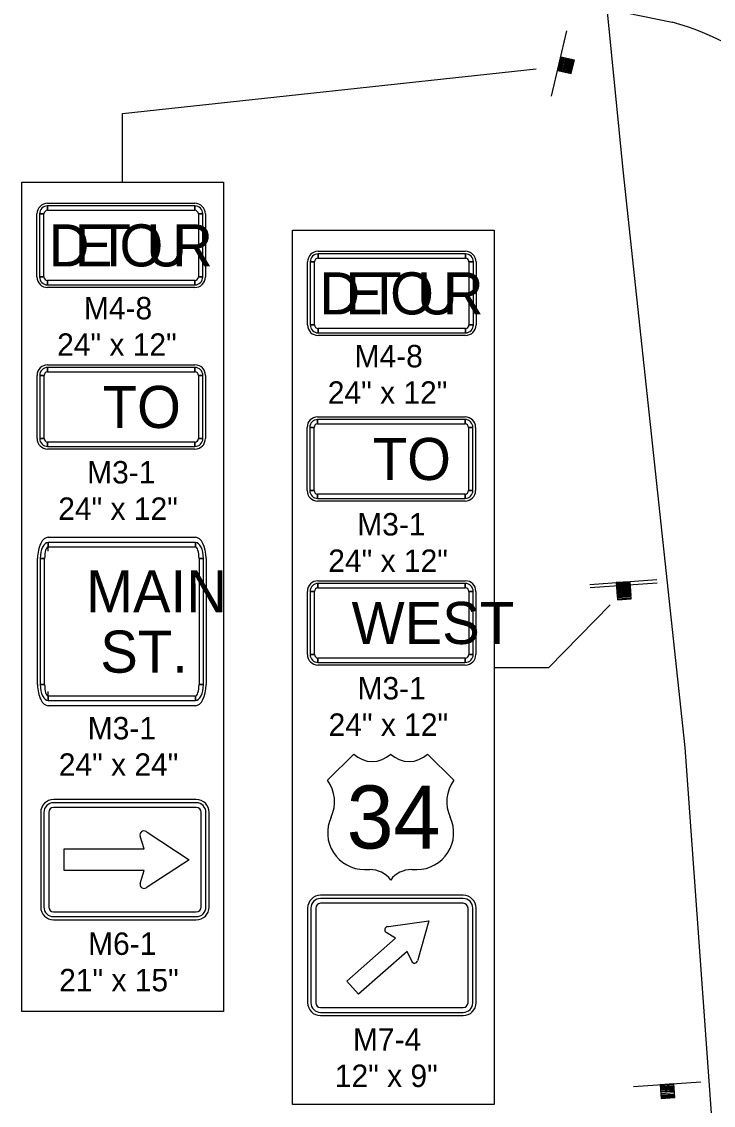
# Model space of a CAD drawing. Extents: x 10133 to 81668, y 6132 to 11018.
# Drawn here: x 11723.8 to 11970.7, y 8730.4 to 9117.3 of the extents above; entities that cross this region are included whole.
import ezdxf

# ---------------------------------------------------------------- set-up
doc = ezdxf.new("R2010")
doc.units = 0
for name, color, linetype in [('dsnTextFinalPlan', 7, 'Continuous'), ('Level 10', 7, 'Continuous'), ('Level 4', 7, 'Continuous'), ('Level 5', 7, 'Continuous')]:
    doc.layers.add(name, color=color, linetype=linetype)

msp = doc.modelspace()

# ---------------------------------------------------------------- linework, layer by layer
at = {"layer": 'dsnTextFinalPlan'}
for p, q in [((11804.44, 9148.37), (11956.07, 9117.16)), ((11912.99, 9090.73), (11918.44, 9114.1)), ((11916.6, 9104.63), (11915.49, 9099.88)), ((11915.73, 9099.82), (11916.84, 9104.57)), ((11917.06, 9104.52), (11915.96, 9099.77)), ((11916.18, 9099.72), (11917.29, 9104.47)), ((11917.48, 9104.42), (11916.37, 9099.67)), ((11916.55, 9099.63), (11917.65, 9104.38)), ((11917.94, 9104.32), (11916.83, 9099.57)), ((11917.06, 9099.51), (11918.16, 9104.26)), ((11918.35, 9104.22), (11917.23, 9099.47)), ((11917.52, 9099.41), (11918.62, 9104.16)), ((11918.94, 9104.08), (11917.84, 9099.33)), ((11918.2, 9099.25), (11919.31, 9104)), ((11919.5, 9103.95), (11918.38, 9099.21)), ((11918.75, 9099.12), (11919.87, 9103.87)), ((11920.04, 9103.83), (11918.94, 9099.08)), ((11919.21, 9099.01), (11920.31, 9103.76)), ((11920.5, 9103.72), (11919.4, 9098.97)), ((11919.67, 9098.91), (11920.78, 9103.66)), ((11926.67, 8916.41), (11950.6, 8918.14)), ((11926.75, 8915.23), (11950.69, 8916.97)), ((11941.01, 8917.08), (11936.15, 8916.73)), ((11936.16, 8916.49), (11941.03, 8916.84)), ((11941.04, 8916.61), (11936.18, 8916.26)), ((11936.2, 8916.03), (11941.06, 8916.38)), ((11941.07, 8916.19), (11936.21, 8915.83)), ((11936.22, 8915.65), (11941.09, 8916.01)), ((11941.09, 8915.91), (11936.23, 8915.56)), ((11941.11, 8915.71), (11936.24, 8915.36)), ((11936.25, 8915.31), (11941.11, 8915.66)), ((11936.26, 8915.13), (11941.13, 8915.48)), ((11941.13, 8915.44), (11936.27, 8915.08)), ((11941.14, 8915.29), (11936.27, 8914.95)), ((11936.28, 8914.85), (11941.15, 8915.21)), ((11941.16, 8915.01), (11936.3, 8914.66)), ((11936.3, 8914.66), (11941.16, 8915.01)), ((11936.31, 8914.48), (11941.17, 8914.83)), ((11941.18, 8914.68), (11936.32, 8914.33)), ((11941.19, 8914.54), (11936.33, 8914.19)), ((11936.35, 8913.96), (11941.21, 8914.31)), ((11936.35, 8913.96), (11941.21, 8914.31)), ((11941.23, 8914.11), (11936.36, 8913.78)), ((11941.23, 8914.11), (11936.36, 8913.78)), ((11936.38, 8913.48), (11941.25, 8913.84)), ((11936.39, 8913.4), (11941.25, 8913.74)), ((11941.27, 8913.56), (11936.4, 8913.21)), ((11941.27, 8913.51), (11936.4, 8913.16)), ((11936.42, 8912.93), (11941.29, 8913.28)), ((11936.43, 8912.78), (11941.3, 8913.13)), ((11941.3, 8913.09), (11936.44, 8912.73)), ((11941.31, 8912.94), (11936.45, 8912.6)), ((11936.46, 8912.45), (11941.32, 8912.81)), ((11936.47, 8912.23), (11941.34, 8912.56)), ((11941.35, 8912.38), (11936.49, 8912.03)), ((11936.51, 8911.75), (11941.37, 8912.11)), ((11941.38, 8911.91), (11936.52, 8911.56)), ((11936.54, 8911.28), (11941.41, 8911.63)), ((11881.44, 8805.37), (11830.48, 8805.37)), ((11825.9, 8800.79), (11825.9, 8767)), ((11886.03, 8767), (11886.03, 8800.79)), ((11830.48, 8762.42), (11881.44, 8762.42)), ((11942.28, 8737.1), (11966.22, 8738.78)), ((11956.63, 8737.75), (11951.76, 8737.41)), ((11951.78, 8737.16), (11956.64, 8737.5)), ((11956.66, 8737.27), (11951.79, 8736.93)), ((11951.81, 8736.7), (11956.68, 8737.05)), ((11956.69, 8736.85), (11951.82, 8736.51)), ((11951.84, 8736.33), (11956.7, 8736.67)), ((11956.72, 8736.38), (11951.86, 8736.04)), ((11951.87, 8735.81), (11956.74, 8736.15)), ((11956.75, 8735.95), (11951.89, 8735.63)), ((11951.91, 8735.33), (11956.77, 8735.67)), ((11956.79, 8735.35), (11951.93, 8735.01)), ((11951.96, 8734.63), (11956.82, 8734.97)), ((11956.83, 8734.78), (11951.97, 8734.45)), ((11951.99, 8734.08), (11956.86, 8734.4)), ((11956.87, 8734.22), (11952.01, 8733.88)), ((11952.03, 8733.6), (11956.89, 8733.94)), ((11956.91, 8733.75), (11952.04, 8733.41)), ((11952.06, 8733.13), (11956.93, 8733.47))]:
    msp.add_line(p, q, dxfattribs=at)
for points in [[(11924.53, 9208.75), (11924.53, 9205.04), (11938.44, 9064.44), (11960.57, 8858.09), (11970.22, 8724.25)], [(11759.83, 9059.99), (11759.83, 9084.49), (11907.51, 9100.55)], [(11892.49, 8886.75), (11912, 8886.75), (11933.91, 8909.07)], [(11854.74, 8794.23), (11869.11, 8796.3), (11865.25, 8782.32)], [(11863.04, 8781.81), (11861.41, 8785.32), (11844.09, 8770.03), (11839.93, 8774.74), (11857.26, 8790.03), (11853.96, 8792.06)]]:
    msp.add_lwpolyline(points, dxfattribs=at)
for points in [[(11916.33, 9104.69), (11915.22, 9099.91), (11920, 9098.8), (11921.11, 9103.58)], [(11723.8, 9059.99), (11795.86, 9059.99), (11795.86, 8763.89), (11723.8, 8763.89)], [(11723.8, 9059.99), (11795.86, 9059.99), (11795.86, 8763.89), (11723.8, 8763.89)], [(11820.43, 9042.86), (11892.49, 9042.86), (11892.49, 8730.63), (11820.43, 8730.63)], [(11820.43, 9042.86), (11892.49, 9042.86), (11892.49, 8730.63), (11820.43, 8730.63)], [(11940.99, 8917.36), (11936.09, 8917.01), (11936.45, 8912.11), (11941.34, 8912.46)], [(11941.07, 8916.19), (11936.18, 8915.83), (11936.53, 8910.93), (11941.43, 8911.29)], [(11956.61, 8738.02), (11951.71, 8737.68), (11952.05, 8732.78), (11956.95, 8733.13)]]:
    msp.add_lwpolyline(points, close=True, dxfattribs=at)
for centre, radius, start, end in [((11932.89, 9030.85), 89.37, 17.4357, 74.9717), ((11830.48, 8800.79), 4.58, 90, 180), ((11881.44, 8800.79), 4.58, 360, 90), ((11854.58, 8793.04), 1.16, 98.0346, 237.3927), ((11838.21, 8909.01), 115.96, 278.0346, 278.1951), ((11864.06, 8782.3), 1.14, 205.4546, 344.7341), ((11977.03, 8751.46), 115.96, 164.5667, 164.7341), ((11830.48, 8767), 4.58, 180, 270), ((11881.44, 8767), 4.58, 270, 0)]:
    msp.add_arc(centre, radius, start, end, dxfattribs=at)
at = {"layer": 'Level 10'}
for p, q in [((11733.01, 9052.48), (11785.62, 9052.48)), ((11733.01, 9049.97), (11733.01, 9051.54)), ((11785.62, 9051.54), (11785.62, 9049.97)), ((11729.25, 9026.17), (11729.25, 9048.72)), ((11730.19, 9048.72), (11731.75, 9048.72)), ((11786.87, 9048.72), (11788.44, 9048.72)), ((11789.38, 9048.72), (11789.38, 9026.17)), ((11829.63, 9035.35), (11882.25, 9035.35)), ((11829.63, 9032.84), (11829.63, 9034.41)), ((11882.25, 9034.41), (11882.25, 9032.84)), ((11825.88, 9009.04), (11825.88, 9031.59)), ((11826.82, 9031.59), (11828.38, 9031.59)), ((11883.5, 9031.59), (11885.07, 9031.59)), ((11886.01, 9031.59), (11886.01, 9009.04)), ((11731.75, 9026.17), (11730.19, 9026.17)), ((11733.01, 9023.35), (11733.01, 9024.92)), ((11785.62, 9024.92), (11785.62, 9023.35)), ((11788.44, 9026.17), (11786.87, 9026.17)), ((11785.62, 9022.41), (11733.01, 9022.41)), ((11828.38, 9009.04), (11826.82, 9009.04)), ((11885.07, 9009.04), (11883.5, 9009.04)), ((11829.63, 9006.22), (11829.63, 9007.79)), ((11882.25, 9005.28), (11829.63, 9005.28)), ((11882.25, 9007.79), (11882.25, 9006.22)), ((11733.05, 8994.79), (11785.66, 8994.79)), ((11733.05, 8992.29), (11733.05, 8993.85)), ((11785.66, 8993.85), (11785.66, 8992.29)), ((11729.29, 8968.48), (11729.29, 8991.03)), ((11730.23, 8991.03), (11731.8, 8991.03)), ((11786.92, 8991.03), (11788.48, 8991.03)), ((11789.42, 8991.03), (11789.42, 8968.48)), ((11829.47, 8976.2), (11882.08, 8976.2)), ((11829.47, 8973.7), (11829.47, 8975.26)), ((11882.08, 8975.26), (11882.08, 8973.7)), ((11825.71, 8949.9), (11825.71, 8972.45)), ((11826.65, 8972.45), (11828.22, 8972.45)), ((11883.34, 8972.45), (11884.9, 8972.45)), ((11885.84, 8972.45), (11885.84, 8949.9)), ((11731.8, 8968.48), (11730.23, 8968.48)), ((11733.05, 8965.67), (11733.05, 8967.23)), ((11785.66, 8967.23), (11785.66, 8965.67)), ((11788.48, 8968.48), (11786.92, 8968.48)), ((11785.66, 8964.73), (11733.05, 8964.73)), ((11828.22, 8949.9), (11826.65, 8949.9)), ((11829.47, 8947.08), (11829.47, 8948.64)), ((11882.08, 8948.64), (11882.08, 8947.08)), ((11884.9, 8949.9), (11883.34, 8949.9)), ((11882.08, 8946.14), (11829.47, 8946.14)), ((11733.24, 8933.21), (11785.86, 8933.21)), ((11733.24, 8928.2), (11733.24, 8931.33)), ((11785.86, 8931.33), (11785.86, 8929.76)), ((11729.48, 8880.59), (11729.48, 8925.69)), ((11730.42, 8925.69), (11731.99, 8925.69)), ((11787.11, 8925.69), (11788.67, 8925.69)), ((11789.61, 8925.69), (11789.61, 8880.59)), ((11829.58, 8917.66), (11882.19, 8917.66)), ((11829.58, 8915.15), (11829.58, 8916.72)), ((11882.19, 8916.72), (11882.19, 8915.15)), ((11825.82, 8891.35), (11825.82, 8913.9)), ((11826.76, 8913.9), (11828.33, 8913.9)), ((11883.44, 8913.9), (11885.01, 8913.9)), ((11885.95, 8913.9), (11885.95, 8891.35)), ((11828.33, 8891.35), (11826.76, 8891.35)), ((11829.58, 8888.53), (11829.58, 8890.1)), ((11882.19, 8890.1), (11882.19, 8888.53)), ((11885.01, 8891.35), (11883.44, 8891.35)), ((11882.19, 8887.59), (11829.58, 8887.59)), ((11731.99, 8880.59), (11730.42, 8880.59)), ((11733.24, 8874.96), (11733.24, 8878.09)), ((11788.67, 8880.59), (11787.11, 8880.59)), ((11785.86, 8876.52), (11785.86, 8874.96)), ((11785.86, 8873.08), (11733.24, 8873.08)), ((11786.14, 8839.55), (11735.17, 8839.55)), ((11786.14, 8838.41), (11735.17, 8838.41)), ((11730.59, 8834.97), (11730.59, 8801.18)), ((11731.73, 8834.97), (11731.73, 8801.18)), ((11733.45, 8834.97), (11733.45, 8801.18)), ((11786.14, 8836.69), (11735.17, 8836.69)), ((11787.85, 8801.18), (11787.85, 8834.97)), ((11789.57, 8801.18), (11789.57, 8834.97)), ((11790.72, 8801.18), (11790.72, 8834.97)), ((11881.44, 8804.22), (11830.48, 8804.22)), ((11827.04, 8800.79), (11827.04, 8767)), ((11828.76, 8800.79), (11828.76, 8767)), ((11881.44, 8802.5), (11830.48, 8802.5)), ((11883.16, 8767), (11883.16, 8800.79)), ((11884.88, 8767), (11884.88, 8800.79)), ((11735.17, 8799.47), (11786.14, 8799.47)), ((11735.17, 8797.75), (11786.14, 8797.75)), ((11735.17, 8796.6), (11786.14, 8796.6)), ((11830.48, 8765.28), (11881.44, 8765.28)), ((11830.48, 8763.56), (11881.44, 8763.56))]:
    msp.add_line(p, q, dxfattribs=at)
for points in [[(11785.62, 9051.54), (11733.01, 9051.54), (11733.01, 9049.97), (11785.62, 9049.97), (11785.62, 9051.54)], [(11730.19, 9048.72), (11730.19, 9026.17), (11731.75, 9026.17), (11731.75, 9048.72), (11730.19, 9048.72)], [(11788.44, 9026.17), (11788.44, 9048.72), (11786.87, 9048.72), (11786.87, 9026.17), (11788.44, 9026.17)], [(11882.25, 9034.41), (11829.63, 9034.41), (11829.63, 9032.84), (11882.25, 9032.84), (11882.25, 9034.41)], [(11826.82, 9031.59), (11826.82, 9009.04), (11828.38, 9009.04), (11828.38, 9031.59), (11826.82, 9031.59)], [(11885.07, 9009.04), (11885.07, 9031.59), (11883.5, 9031.59), (11883.5, 9009.04), (11885.07, 9009.04)], [(11733.01, 9023.35), (11785.62, 9023.35), (11785.62, 9024.92), (11733.01, 9024.92), (11733.01, 9023.35)], [(11829.63, 9006.22), (11882.25, 9006.22), (11882.25, 9007.79), (11829.63, 9007.79), (11829.63, 9006.22)], [(11785.66, 8993.85), (11733.05, 8993.85), (11733.05, 8992.29), (11785.66, 8992.29), (11785.66, 8993.85)], [(11730.23, 8991.03), (11730.23, 8968.48), (11731.8, 8968.48), (11731.8, 8991.03), (11730.23, 8991.03)], [(11788.48, 8968.48), (11788.48, 8991.03), (11786.92, 8991.03), (11786.92, 8968.48), (11788.48, 8968.48)], [(11882.08, 8975.26), (11829.47, 8975.26), (11829.47, 8973.7), (11882.08, 8973.7), (11882.08, 8975.26)], [(11826.65, 8972.45), (11826.65, 8949.9), (11828.22, 8949.9), (11828.22, 8972.45), (11826.65, 8972.45)], [(11884.9, 8949.9), (11884.9, 8972.45), (11883.34, 8972.45), (11883.34, 8949.9), (11884.9, 8949.9)], [(11733.05, 8965.67), (11785.66, 8965.67), (11785.66, 8967.23), (11733.05, 8967.23), (11733.05, 8965.67)], [(11829.47, 8947.08), (11882.08, 8947.08), (11882.08, 8948.64), (11829.47, 8948.64), (11829.47, 8947.08)], [(11785.86, 8931.33), (11733.24, 8931.33), (11733.24, 8929.76), (11785.86, 8929.76), (11785.86, 8931.33)], [(11730.42, 8925.69), (11730.42, 8880.59), (11731.99, 8880.59), (11731.99, 8925.69), (11730.42, 8925.69)], [(11788.67, 8880.59), (11788.67, 8925.69), (11787.11, 8925.69), (11787.11, 8880.59), (11788.67, 8880.59)], [(11882.19, 8916.72), (11829.58, 8916.72), (11829.58, 8915.15), (11882.19, 8915.15), (11882.19, 8916.72)], [(11826.76, 8913.9), (11826.76, 8891.35), (11828.33, 8891.35), (11828.33, 8913.9), (11826.76, 8913.9)], [(11885.01, 8891.35), (11885.01, 8913.9), (11883.44, 8913.9), (11883.44, 8891.35), (11885.01, 8891.35)], [(11829.58, 8888.53), (11882.19, 8888.53), (11882.19, 8890.1), (11829.58, 8890.1), (11829.58, 8888.53)], [(11733.24, 8874.96), (11785.86, 8874.96), (11785.86, 8876.52), (11733.24, 8876.52), (11733.24, 8874.96)]]:
    msp.add_lwpolyline(points, close=True, dxfattribs=at)
for points in [[(11768.57, 8827.9), (11783.56, 8818.08), (11768.57, 8808.29)], [(11766.1, 8809.62), (11767.47, 8814.2), (11738.94, 8814.2), (11738.94, 8821.96), (11767.47, 8821.96), (11766.07, 8826.53)]]:
    msp.add_lwpolyline(points, dxfattribs=at)
for centre, radius, start, end in [((11733.01, 9048.72), 3.76, 90, 180), ((11733.01, 9048.72), 2.82, 90.0002, 179.9998), ((11785.62, 9048.72), 3.76, 0, 90), ((11785.62, 9048.72), 2.82, 0, 90.0002), ((11733.01, 9048.72), 1.25, 90.0002, 179.9998), ((11785.62, 9048.72), 1.25, 0, 90.0002), ((11829.63, 9031.59), 3.76, 90, 180), ((11829.63, 9031.59), 2.82, 90.0002, 179.9998), ((11829.63, 9031.59), 1.25, 90.0002, 179.9998), ((11882.25, 9031.59), 3.76, 0, 90), ((11882.25, 9031.59), 2.82, 0, 90.0002), ((11882.25, 9031.59), 1.25, 0, 90.0002), ((11733.01, 9026.17), 3.76, 180, 270), ((11733.01, 9026.17), 2.82, 179.9998, 270.0001), ((11733.01, 9026.17), 1.25, 179.9998, 270.0001), ((11785.62, 9026.17), 2.82, 270.0001, 0.0003), ((11785.62, 9026.17), 1.25, 270.0001, 0.0003), ((11785.62, 9026.17), 3.76, 270, 359.9911), ((11829.63, 9009.04), 3.76, 180, 270), ((11829.63, 9009.04), 2.82, 179.9998, 270.0001), ((11829.63, 9009.04), 1.25, 179.9998, 270.0001), ((11882.25, 9009.04), 2.82, 270.0001, 0.0003), ((11882.25, 9009.04), 1.25, 270.0001, 0.0003), ((11882.25, 9009.04), 3.76, 270, 359.9911), ((11733.05, 8991.03), 3.76, 90, 180), ((11733.05, 8991.03), 2.82, 90.0002, 179.9998), ((11785.66, 8991.03), 3.76, 0, 90), ((11785.66, 8991.03), 2.82, 0, 90.0002), ((11733.05, 8991.03), 1.25, 90.0002, 179.9998), ((11785.66, 8991.03), 1.25, 0, 90.0002), ((11829.47, 8972.45), 3.76, 90, 180), ((11829.47, 8972.45), 2.82, 90.0002, 179.9998), ((11882.08, 8972.45), 3.76, 0, 90), ((11882.08, 8972.45), 2.82, 0, 90.0002), ((11829.47, 8972.45), 1.25, 90.0002, 179.9998), ((11882.08, 8972.45), 1.25, 0, 90.0002), ((11733.05, 8968.48), 3.76, 180, 270), ((11733.05, 8968.48), 2.82, 179.9998, 270.0001), ((11733.05, 8968.48), 1.25, 179.9998, 270.0001), ((11785.66, 8968.48), 2.82, 270.0001, 0.0003), ((11785.66, 8968.48), 1.25, 270.0001, 0.0003), ((11785.66, 8968.48), 3.76, 270, 359.9911), ((11829.47, 8949.9), 3.76, 180, 270), ((11829.47, 8949.9), 2.82, 179.9998, 270.0001), ((11829.47, 8949.9), 1.25, 179.9998, 270.0001), ((11882.08, 8949.9), 2.82, 270.0001, 0.0003), ((11882.08, 8949.9), 1.25, 270.0001, 0.0003), ((11882.08, 8949.9), 3.76, 270, 359.9911), ((11829.58, 8913.9), 3.76, 90, 180), ((11829.58, 8913.9), 2.82, 90.0002, 179.9998), ((11882.19, 8913.9), 3.76, 0, 90), ((11882.19, 8913.9), 2.82, 0, 90.0002), ((11829.58, 8913.9), 1.25, 90.0002, 179.9998), ((11882.19, 8913.9), 1.25, 0, 90.0002), ((11829.58, 8891.35), 3.76, 180, 270), ((11829.58, 8891.35), 2.82, 179.9998, 270.0001), ((11829.58, 8891.35), 1.25, 179.9998, 270.0001), ((11882.19, 8891.35), 2.82, 270.0001, 0.0003), ((11882.19, 8891.35), 1.25, 270.0001, 0.0003), ((11882.19, 8891.35), 3.76, 270, 359.9911), ((11735.17, 8834.97), 4.58, 90, 180), ((11735.17, 8834.97), 3.44, 90, 180), ((11786.14, 8834.97), 4.58, 360, 90), ((11786.14, 8834.97), 3.44, 0, 90), ((11735.17, 8834.97), 1.72, 90, 180), ((11786.14, 8834.97), 1.72, 0, 90), ((11767.45, 8826.92), 1.43, 56.6109, 195.9691), ((11847.02, 8947.65), 143.16, 236.6109, 236.7714), ((11767.45, 8809.23), 1.4, 164.0309, 303.3104), ((11846.84, 8688.42), 143.16, 123.143, 123.3104), ((11830.48, 8800.79), 3.44, 90, 180), ((11881.44, 8800.79), 3.44, 0, 90), ((11735.17, 8801.18), 4.58, 180, 270), ((11735.17, 8801.18), 3.44, 180, 270), ((11735.17, 8801.18), 1.72, 180, 270), ((11786.14, 8801.18), 4.58, 270, 0), ((11786.14, 8801.18), 3.44, 270, 360), ((11786.14, 8801.18), 1.72, 270, 0), ((11830.48, 8800.79), 1.72, 90, 180), ((11881.44, 8800.79), 1.72, 0, 90), ((11830.48, 8767), 3.44, 180, 270), ((11830.48, 8767), 1.72, 180, 270), ((11881.44, 8767), 3.44, 270, 360), ((11881.44, 8767), 1.72, 270, 0)]:
    msp.add_arc(centre, radius, start, end, dxfattribs=at)
for centre, major_axis, ratio, start_param, end_param in [((11733.24, 8925.69), (0, 7.52), 0.5, 6.283185, 7.853982), ((11733.24, 8925.69), (0, 5.64), 0.5, 0.000004, 1.570794), ((11785.86, 8925.69), (0, 7.52), 0.5, 4.712389, 6.283185), ((11785.86, 8925.69), (0, 5.64), 0.5, 4.712389, 6.283189), ((11733.24, 8925.69), (0, 4.07), 0.307692, 0.000004, 1.570794), ((11785.86, 8925.69), (0, 4.07), 0.307692, 4.712389, 6.283189), ((11733.24, 8880.59), (0, 7.52), 0.5, 1.570796, 3.141593), ((11733.24, 8880.59), (0, 5.64), 0.5, 1.570794, 3.141594), ((11733.24, 8880.59), (0, 4.07), 0.307692, 1.570794, 3.141594), ((11785.86, 8880.59), (0, 5.64), 0.5, 3.141594, 4.712394), ((11785.86, 8880.59), (0, 4.07), 0.307692, 3.141594, 4.712394), ((11785.86, 8880.59), (0, 7.52), 0.5, 3.141593, 4.712234)]:
    msp.add_ellipse(centre, major_axis=major_axis, ratio=ratio, start_param=start_param, end_param=end_param, dxfattribs=at)
at = {"layer": 'Level 4'}
for p, q in [((11842.41, 8855.82), (11833.04, 8846.45)), ((11842.41, 8855.82), (11833.04, 8846.45)), ((11878.04, 8846.45), (11868.66, 8855.82)), ((11878.04, 8846.45), (11868.66, 8855.82)), ((11846.16, 8814.57), (11848.04, 8814.57)), ((11846.16, 8814.57), (11848.04, 8814.57)), ((11863.04, 8814.57), (11864.91, 8814.57)), ((11863.04, 8814.57), (11864.91, 8814.57))]:
    msp.add_line(p, q, dxfattribs=at)
for centre, radius, start, end in [((11848.97, 8862.52), 9.38, 225.5729, 314.4272), ((11848.97, 8862.52), 9.38, 225.5729, 314.4272), ((11862.1, 8862.52), 9.38, 225.5729, 314.4272), ((11862.1, 8862.52), 9.38, 225.5729, 314.4272), ((11822.37, 8838.79), 13.13, 334.9895, 35.6629), ((11822.37, 8838.79), 13.13, 334.9895, 35.6629), ((11888.7, 8838.79), 13.13, 144.3372, 205.01), ((11888.7, 8838.79), 13.13, 144.3372, 205.01), ((11846.16, 8827.7), 13.13, 154.9897, 270.0001), ((11846.16, 8827.7), 13.13, 154.9897, 270.0001), ((11864.91, 8827.7), 13.13, 270.0001, 25.0104), ((11864.91, 8827.7), 13.13, 270.0001, 25.0104), ((11848.04, 8805.2), 9.38, 36.8699, 90.0002), ((11848.04, 8805.2), 9.38, 36.8699, 90.0002), ((11863.04, 8805.2), 9.38, 90.0002, 143.13), ((11863.04, 8805.2), 9.38, 90.0002, 143.13)]:
    msp.add_arc(centre, radius, start, end, dxfattribs=at)

# ---------------------------------------------------------------- texts
at = {"layer": 'Level 10'}
for s, height, p in [('D', 15.03, (11733.49, 9029.93)), ('E', 15.03, (11742.73, 9029.93)), ('T', 15.03, (11750.51, 9029.93)), ('O', 15.03, (11758.72, 9029.93)), ('U', 15.03, (11768.31, 9029.93)), ('R', 15.03, (11777.54, 9029.93)), ('O', 15.03, (11855.34, 9012.8)), ('D', 15.03, (11830.12, 9012.8)), ('E', 15.03, (11839.36, 9012.8)), ('T', 15.03, (11847.14, 9012.8)), ('U', 15.03, (11864.94, 9012.8)), ('R', 15.03, (11874.17, 9012.8)), ('TO', 15.032, (11752.72, 8972.24)), ('TO', 15.032, (11849.14, 8953.66)), ('MAIN', 15.032, (11746.81, 8906.39)), ('WEST', 15.032, (11841.56, 8895.11)), ('ST.', 15.032, (11751.86, 8884.86))]:
    msp.add_text(s, height=height, dxfattribs=at).set_placement(p)
at = {"layer": 'Level 4'}
msp.add_text('34', height=22.5, dxfattribs=at).set_placement((11839.83, 8822.07))
msp.add_text('34', height=22.5, dxfattribs=at).set_placement((11839.83, 8822.07))
at = {"layer": 'Level 5'}
for s, p in [('M4-8', (11746.01, 9011.03)), ('24" x 12"', (11736.46, 8998.03)), ('M4-8', (11842.64, 8993.9)), ('24" x 12"', (11833.09, 8980.9)), ('M3-1', (11747.18, 8952.43)), ('24" x 12"', (11736.85, 8939.43)), ('M3-1', (11843.6, 8933.85)), ('24" x 12"', (11833.27, 8920.85)), ('M3-1', (11843.7, 8875.3)), ('24" x 12"', (11833.37, 8862.3)), ('M3-1', (11747.37, 8861.04)), ('24" x 24"', (11737.04, 8848.04)), ('M6-1', (11747.52, 8784.09)), ('21" x 15"', (11737.18, 8771.09)), ('M7-4', (11842.07, 8749.91)), ('12" x 9"', (11835.6, 8736.91))]:
    msp.add_text(s, height=8, dxfattribs=at).set_placement(p)

doc.saveas('drawing.dxf')
